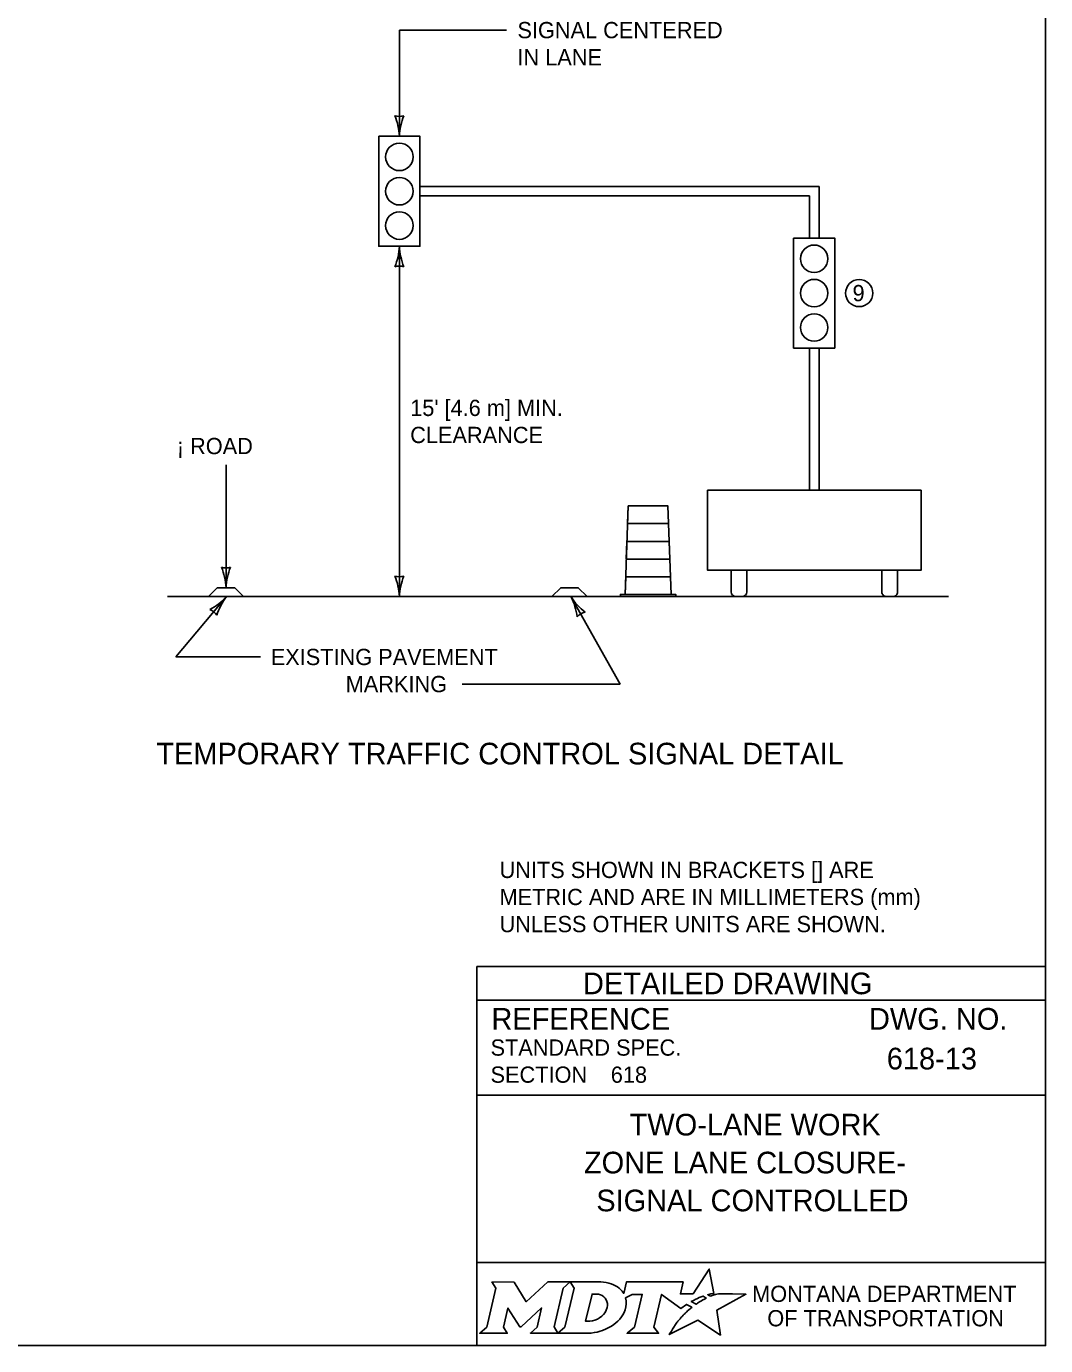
# Model space of a CAD drawing. Extents: x 49991.4 to 50021, y 49987.6 to 50011.4.
# Drawn here: x 50004.851 to 50008.615, y 50000.062 to 50004.934 of the extents above; entities that cross this region are included whole.
import ezdxf

# ---------------------------------------------------------------- set-up
doc = ezdxf.new("R2010")
doc.units = 0
for name, color, linetype in [('Level 1', 7, 'Continuous'), ('Level 2', 7, 'Continuous'), ('Level 3', 7, 'Continuous')]:
    doc.layers.add(name, color=color, linetype=linetype)

msp = doc.modelspace()

# ---------------------------------------------------------------- linework, layer by layer
at = {"layer": 'Level 1'}
for p, q in [((50006.3043, 50004.3423), (50007.778, 50004.3423)), ((50007.778, 50004.3423), (50007.778, 50004.1518)), ((50007.7432, 50004.3075), (50006.3043, 50004.3075)), ((50007.7432, 50004.1518), (50007.7432, 50004.3075)), ((50007.7432, 50003.7458), (50007.7432, 50003.2207)), ((50007.778, 50003.7458), (50007.778, 50003.2207)), ((50007.2224, 50003.0975), (50007.0709, 50003.0975)), ((50007.2224, 50003.0975), (50007.0709, 50003.0975)), ((50007.0663, 50002.9669), (50007.0686, 50003.0322)), ((50007.2247, 50003.0322), (50007.0686, 50003.0322)), ((50007.0686, 50003.0322), (50007.2247, 50003.0322)), ((50007.2247, 50003.0322), (50007.227, 50002.9669)), ((50007.227, 50002.9669), (50007.0663, 50002.9669)), ((50007.227, 50002.9669), (50007.0663, 50002.9669)), ((50007.4533, 50002.9255), (50007.4533, 50002.8455)), ((50007.5113, 50002.9255), (50007.5113, 50002.8455)), ((50008.01, 50002.9255), (50008.01, 50002.8455)), ((50008.068, 50002.9255), (50008.068, 50002.8455)), ((50005.5232, 50002.8281), (50005.556, 50002.8609)), ((50005.556, 50002.8609), (50005.6202, 50002.8609)), ((50005.6202, 50002.8609), (50005.6531, 50002.8281)), ((50006.7916, 50002.8281), (50006.8244, 50002.8609)), ((50006.8244, 50002.8609), (50006.8886, 50002.8609)), ((50006.8886, 50002.8609), (50006.9214, 50002.8281)), ((50007.2293, 50002.9016), (50007.064, 50002.9016)), ((50007.2293, 50002.9016), (50007.0679, 50002.9016)), ((50007.0679, 50002.9016), (50007.2293, 50002.9016)), ((50005.3716, 50002.8281), (50008.2556, 50002.8281)), ((50007.4707, 50002.8281), (50007.4939, 50002.8281))]:
    msp.add_line(p, q, dxfattribs=at)
for points in [[(50008.6146, 50011.2628), (50000.3356, 50011.2628), (50000.3356, 50000.0624), (50008.6146, 50000.0624)], [(50006.1521, 50004.5278), (50006.3043, 50004.5278), (50006.3043, 50004.1219), (50006.1521, 50004.1219)], [(50007.6839, 50004.1518), (50007.8362, 50004.1518), (50007.8362, 50003.7458), (50007.6839, 50003.7458)], [(50007.3663, 50003.2207), (50008.155, 50003.2207), (50008.155, 50002.9255), (50007.3663, 50002.9255)], [(50007.2316, 50002.8363), (50007.0617, 50002.8363), (50007.0731, 50003.1629), (50007.2201, 50003.1629)], [(50007.2293, 50002.9016), (50007.2316, 50002.8363), (50007.0617, 50002.8363), (50007.064, 50002.9016), (50007.2254, 50002.9016)], [(50007.0446, 50002.8281), (50007.2487, 50002.8281), (50007.2487, 50002.8363), (50007.0446, 50002.8363)]]:
    msp.add_lwpolyline(points, close=True, dxfattribs=at)
for points in [[(50007.0709, 50003.0975), (50007.0731, 50003.1629), (50007.2201, 50003.1629), (50007.2224, 50003.0975)], [(50005.5901, 50002.8281), (50005.6531, 50002.8281), (50005.6202, 50002.8609), (50005.556, 50002.8609), (50005.5232, 50002.8281), (50005.5901, 50002.8281)], [(50006.8619, 50002.8281), (50006.9214, 50002.8281), (50006.8886, 50002.8609), (50006.8244, 50002.8609), (50006.7916, 50002.8281), (50006.8619, 50002.8281)]]:
    msp.add_lwpolyline(points, dxfattribs=at)
for centre in [(50006.2282, 50004.4517), (50006.2282, 50004.3249), (50006.2282, 50004.198), (50007.76, 50004.0756), (50007.76, 50003.9488), (50007.76, 50003.8219)]:
    msp.add_circle(centre, 0.0507, dxfattribs=at)
for centre, start, end in [((50007.4707, 50002.8455), 180, 270), ((50007.4939, 50002.8455), 270.0107, 0.0007), ((50008.0274, 50002.8455), 179.9955, 270.0346), ((50008.0506, 50002.8455), 269.9827, 0.0045)]:
    msp.add_arc(centre, 0.0174, start, end, dxfattribs=at)
at = {"layer": 'Level 2'}
for p, q in [((50008.6146, 50001.4624), (50006.5146, 50001.4624)), ((50006.5146, 50001.4624), (50006.5146, 50000.0624)), ((50008.6146, 50001.3374), (50006.5146, 50001.3374)), ((50008.2507, 50001.1223), (50008.2507, 50001.1223)), ((50007.0089, 50001.0629), (50007.0089, 50001.0629)), ((50008.6146, 50000.9874), (50006.5146, 50000.9874)), ((50007.5646, 50000.7383), (50007.5646, 50000.7383)), ((50008.6146, 50000.3693), (50006.5146, 50000.3693))]:
    msp.add_line(p, q, dxfattribs=at)
for points in [[(50007.3771, 50000.2447), (50007.3668, 50000.2503), (50007.3784, 50000.2531), (50007.39, 50000.2551), (50007.3726, 50000.3452), (50007.3131, 50000.2539), (50007.2658, 50000.2532), (50007.2761, 50000.2973), (50007.0669, 50000.2974), (50007.0568, 50000.2549), (50007.051, 50000.2632)], [(50006.5701, 50000.2974), (50006.5842, 50000.274), (50006.5507, 50000.1307), (50006.525, 50000.1082), (50006.6266, 50000.1082), (50006.6131, 50000.131), (50006.6293, 50000.2011), (50006.673, 50000.1321), (50006.6783, 50000.1321), (50006.7534, 50000.2016), (50006.737, 50000.1305), (50006.7123, 50000.1085), (50006.8139, 50000.1085), (50006.8001, 50000.1318), (50006.8333, 50000.2742)], [(50006.8333, 50000.2742), (50006.8586, 50000.2974), (50006.7762, 50000.2974), (50006.6966, 50000.2244), (50006.6521, 50000.2971), (50006.5701, 50000.2974)], [(50006.9722, 50000.2974), (50006.8586, 50000.2974), (50006.8733, 50000.2745), (50006.8394, 50000.1307), (50006.8139, 50000.1085), (50006.9245, 50000.1085)], [(50006.9962, 50000.2107), (50006.995, 50000.2026), (50006.9918, 50000.1933), (50006.9876, 50000.1851), (50006.982, 50000.1776), (50006.9755, 50000.1707), (50006.9676, 50000.1644), (50006.9593, 50000.1597), (50006.9502, 50000.1558), (50006.9411, 50000.1535), (50006.9319, 50000.1526), (50006.916, 50000.1526), (50006.9396, 50000.2526), (50006.9556, 50000.2526), (50006.9632, 50000.252), (50006.9708, 50000.2501), (50006.9774, 50000.2471), (50006.9835, 50000.2429), (50006.9883, 50000.2379), (50006.992, 50000.2319), (50006.9947, 50000.2257), (50006.9963, 50000.2183), (50006.9963, 50000.2153), (50006.9962, 50000.2107)], [(50007.0636, 50000.2383), (50007.0882, 50000.2514), (50007.1251, 50000.2514), (50007.0965, 50000.1309), (50007.069, 50000.1082), (50007.1852, 50000.1082), (50007.1682, 50000.1311), (50007.1964, 50000.2513), (50007.2677, 50000.1996), (50007.2888, 50000.2147), (50007.3085, 50000.2038)], [(50007.2527, 50000.1479), (50007.2374, 50000.1235), (50007.2327, 50000.116), (50007.2269, 50000.1074), (50007.2246, 50000.1031), (50007.3299, 50000.1562), (50007.4138, 50000.1011), (50007.4007, 50000.1938), (50007.5076, 50000.2522), (50007.4583, 50000.253), (50007.4282, 50000.2534), (50007.4074, 50000.2537), (50007.4006, 50000.2522), (50007.3957, 50000.251), (50007.3873, 50000.2487), (50007.3771, 50000.2447)], [(50007.3267, 50000.2171), (50007.3243, 50000.2154), (50007.306, 50000.225), (50007.3163, 50000.2307), (50007.3204, 50000.2329), (50007.329, 50000.2369), (50007.3347, 50000.2395), (50007.3426, 50000.2425), (50007.3499, 50000.2452), (50007.3617, 50000.2378), (50007.3577, 50000.2357), (50007.3531, 50000.2332), (50007.3489, 50000.231), (50007.3439, 50000.2281), (50007.342, 50000.227), (50007.3393, 50000.2254), (50007.3368, 50000.224), (50007.3345, 50000.2224), (50007.3319, 50000.2206), (50007.3292, 50000.2188), (50007.3267, 50000.2171)], [(50006.9702, 50000.1158), (50006.9786, 50000.1184), (50006.9916, 50000.1238), (50007.012, 50000.1348)], [(50007.2666, 50000.164), (50007.2666, 50000.164)]]:
    msp.add_lwpolyline(points, dxfattribs=at)
msp.add_circle((50007.9262, 50003.9488), 0.05, dxfattribs=at)
for centre, radius, start, end in [((50006.9953, 50000.219), 0.0709, 339.5329, 15.8582), ((50006.9513, 50000.2363), 0.1183, 300.9103, 339.1383)]:
    msp.add_arc(centre, radius, start, end, dxfattribs=at)
for centre, major_axis, ratio, start_param, end_param in [((50006.9701, 50000.25), (0.0834, -0.0037), 0.568097, 0.61298, 1.570796), ((50007.0257, 50000.2573), (0.0361, -0.0295), 0.469099, 1.225588, 1.570796), ((50007.2764, 50000.1742), (-0.0098, -0.0102), 0.016458, 3.141593, 6.279097), ((50007.2974, 50000.1941), (-0.0112, -0.0097), 0.021651, 3.157348, 6.283185), ((50007.2597, 50000.1559), (-0.00694, -0.00806), 0.008222, 0, 3.137361), ((50006.9248, 50000.2568), (0, 0.1484), 0.987302, 3.139398, 3.456847)]:
    msp.add_ellipse(centre, major_axis=major_axis, ratio=ratio, start_param=start_param, end_param=end_param, dxfattribs=at)
at = {"layer": 'Level 3'}
for p, q in [((50006.6242, 50004.9199), (50006.2282, 50004.9199)), ((50006.2282, 50004.5278), (50006.2282, 50004.9199)), ((50006.2282, 50004.1219), (50006.2282, 50002.8281)), ((50005.5881, 50002.8609), (50005.5881, 50003.3141)), ((50005.4025, 50002.6052), (50005.5901, 50002.8281)), ((50007.0439, 50002.5052), (50006.8619, 50002.8281)), ((50005.7152, 50002.6052), (50005.4025, 50002.6052)), ((50006.4596, 50002.5052), (50007.0439, 50002.5052))]:
    msp.add_line(p, q, dxfattribs=at)
for centre, radius, start, end in [((50006.2282, 50004.6561), 0.0548, 252.1388, 287.8612), ((50005.9955, 50004.5164), 0.233, 2.8273, 22.0772), ((50006.4503, 50004.5187), 0.2223, 157.456, 177.6395), ((50006.0061, 50004.1311), 0.2223, 337.456, 357.6395), ((50006.4609, 50004.1334), 0.233, 182.8273, 202.0772), ((50006.2282, 50003.9937), 0.0548, 72.1388, 107.8612), ((50005.5881, 50002.9891), 0.0548, 252.1388, 287.8612), ((50005.3554, 50002.8494), 0.233, 2.8273, 22.0772), ((50005.8103, 50002.8518), 0.2223, 157.456, 177.6395), ((50006.2282, 50002.9563), 0.0548, 252.1388, 287.8612), ((50005.9955, 50002.8166), 0.233, 2.8273, 22.0772), ((50006.4503, 50002.8189), 0.2223, 157.456, 177.6395), ((50005.426, 50002.9781), 0.2223, 297.3695, 317.553), ((50005.7755, 50002.687), 0.233, 142.7408, 161.9906), ((50006.6639, 50002.727), 0.2223, 6.8656, 27.0491), ((50007.059, 50002.9524), 0.233, 212.2369, 231.4868), ((50005.5075, 50002.73), 0.0548, 32.0523, 67.7746), ((50006.9249, 50002.7164), 0.0548, 101.5484, 137.2708)]:
    msp.add_arc(centre, radius, start, end, dxfattribs=at)

# ---------------------------------------------------------------- texts
at = {"layer": 'Level 2'}
for s, height, p in [('SIGNAL CENTERED', 0.06, (50006.6642, 50004.8899)), ('IN LANE', 0.06, (50006.6642, 50004.7899)), ('9', 0.06, (50007.9016, 50003.9188)), ("15' [4.6 m] MIN.", 0.06, (50006.2682, 50003.495)), ('CLEARANCE', 0.06, (50006.2682, 50003.395)), ('¡ ROAD', 0.06, (50005.4064, 50003.3541)), ('EXISTING PAVEMENT', 0.06, (50005.7532, 50002.5752)), ('MARKING', 0.06, (50006.03, 50002.4752)), ('TEMPORARY TRAFFIC CONTROL SIGNAL DETAIL', 0.08, (50005.3309, 50002.2084)), ('UNITS SHOWN IN BRACKETS [] ARE ', 0.06, (50006.5981, 50001.789)), ('METRIC AND ARE IN MILLIMETERS (mm) ', 0.06, (50006.5981, 50001.689)), ('UNLESS OTHER UNITS ARE SHOWN.', 0.06, (50006.5981, 50001.589)), ('DETAILED DRAWING', 0.0799, (50006.9063, 50001.3599)), ('REFERENCE', 0.08, (50006.5682, 50001.229)), ('DWG. NO.', 0.08, (50007.9624, 50001.229)), ('STANDARD SPEC.', 0.06, (50006.5649, 50001.133)), ('618-13', 0.08, (50008.0281, 50001.0823)), ('SECTION', 0.06, (50006.5649, 50001.033)), ('618', 0.06, (50007.0089, 50001.0329)), (' TWO-LANE WORK', 0.08, (50007.0488, 50000.8383)), ('  ZONE LANE CLOSURE-', 0.08, (50006.8503, 50000.6983)), ('SIGNAL CONTROLLED', 0.08, (50006.9553, 50000.5583)), ('MONTANA DEPARTMENT', 0.06, (50007.5308, 50000.2236)), ('OF TRANSPORTATION', 0.06, (50007.587, 50000.1336))]:
    msp.add_text(s, height=height, dxfattribs=at).set_placement(p)

doc.saveas('drawing.dxf')
